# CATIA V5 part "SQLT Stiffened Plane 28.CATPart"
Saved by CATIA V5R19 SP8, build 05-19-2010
Part number: SQLT Stiffened Plane 28
Publications: "Droite.1", "Plan.1", "Plan.2", "Droite.2", "Droite.3", "Droite.4", "Point.6", "Point.5", "Point.4"
Bounding box of the stored display mesh (mm): x -150 to 150, y 815 to 1100, z 250 to 550
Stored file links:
  G:\EU_thinkMotion\CFAO_2010\MMS_groupe3\MMS_groupe3\A reprendre\fovide\fovide\SQLT Stiffened Plane 28.CATPart
  G:\EU_thinkMotion\CFAO_2010\MMS_groupe3\MMS_groupe3\A reprendre\fovide\fovide\fovide.CATProduct
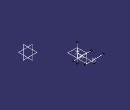
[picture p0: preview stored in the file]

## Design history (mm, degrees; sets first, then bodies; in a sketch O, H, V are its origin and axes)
Set1
  Point1 "Point.F": linked copy from another document
  Point2 "Point.G": linked copy from another document
  Point3 "Point.E": linked copy from another document
Set2 "set Stiffened Plane"
  Line1: type PtPt, FirstPoint Point1, SecondPoint Point2, Start 200
  Plane1: type OffsetPt, RefPlane yz-plane, RefPoint Point1
  Plane2: type OffsetPt, RefPlane xy-plane, RefPoint Point2
  Line2: type Normal, RefPoint Point1, RefSkin Plane1, Start -150, End 150
  Line3: type Normal, RefPoint Point2, RefSkin Plane2, Start -150, End 150
  Line4: type Normal, RefPoint Point3, RefSkin yz-plane, Start -150, End 150
  Point4: type OnCurve, Support Line4, Length 130
  Point5: type OnCurve, Support Line2, Length 130
  Point6: type OnCurve, Support Line3, Length 134
Body1 (main body)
